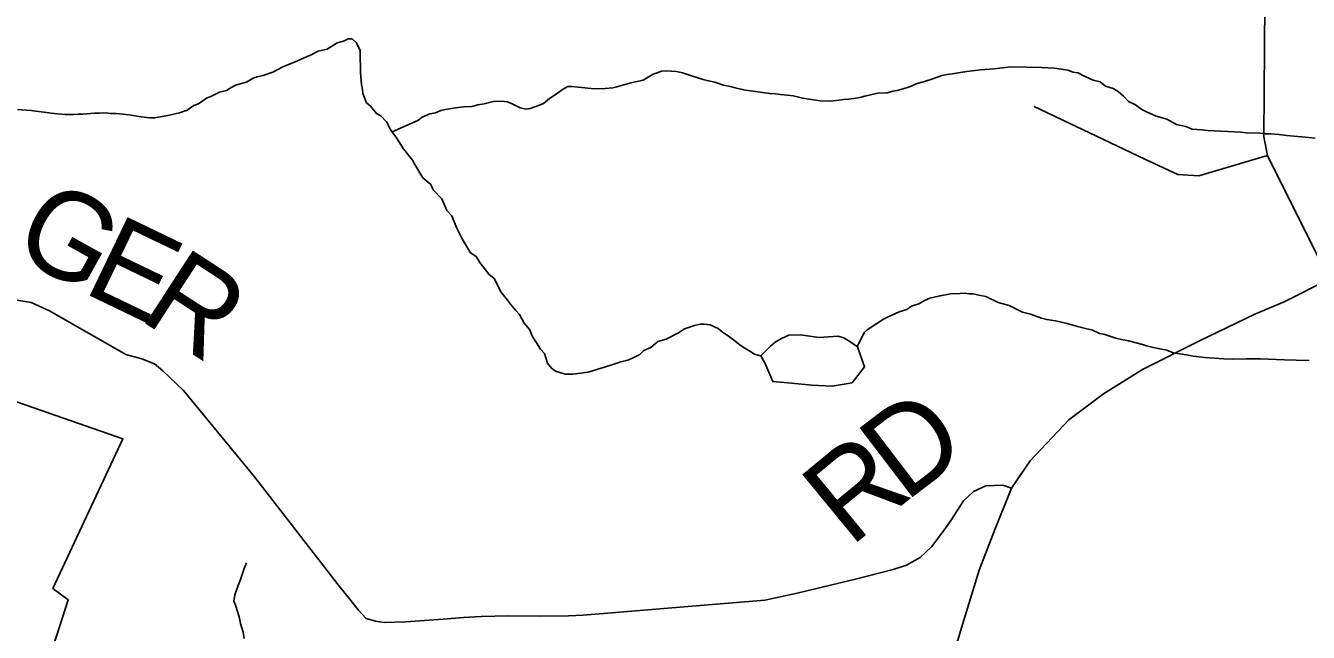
# Model space of a CAD drawing. Extents: x 0 to 34, y 0 to 22.
# Drawn here: x 5.409 to 6.245, y 18.159 to 18.554 of the extents above; entities that cross this region are included whole.
import ezdxf

# ---------------------------------------------------------------- set-up
doc = ezdxf.new("R2010")
doc.units = 0
for name, color, linetype in [('GM_X_Corporation', 7, 'Continuous'), ('GM_X_County_Road', 7, 'Continuous'), ('GM_X_County_Road_Text', 7, 'Continuous'), ('GM_X_Minor_Lake', 7, 'Continuous'), ('GM_X_Minor_River', 7, 'Continuous'), ('GM_X_State_Route', 7, 'Continuous'), ('GM_X_Township_Road', 7, 'Continuous')]:
    doc.layers.add(name, color=color, linetype=linetype)

msp = doc.modelspace()

# ---------------------------------------------------------------- linework, layer by layer
at = {"layer": 'GM_X_Corporation'}
msp.add_lwpolyline([(5.3549, 18.32564), (5.47199, 18.28501), (5.42634, 18.18738), (5.4363, 18.18011), (5.32143, 17.82351)], dxfattribs=at)
at = {"layer": 'GM_X_County_Road'}
for points in [[(5.40285, 18.37527), (5.41202, 18.37394), (5.42418, 18.36853), (5.47376, 18.34003), (5.48429, 18.33709), (5.49254, 18.33384), (5.49773, 18.32953), (5.51151, 18.3165), (5.55767, 18.26031), (5.61323, 18.18866), (5.61971, 18.18073), (5.62535, 18.17342), (5.63061, 18.16777), (5.63663, 18.16609), (5.64229, 18.16519), (5.65629, 18.1658), (5.68067, 18.16749), (5.69403, 18.16847), (5.70553, 18.16913), (5.72358, 18.16956), (5.74326, 18.16929), (5.76254, 18.16962), (5.77202, 18.17013), (5.89051, 18.17992), (5.91147, 18.1843), (5.94961, 18.19356), (5.97403, 18.19975), (5.98282, 18.20255), (5.99167, 18.20764), (5.99906, 18.21465), (6.00639, 18.22433)], [(6.00639, 18.22433), (6.01006, 18.22917), (6.01213, 18.23239), (6.01994, 18.24447), (6.02655, 18.25075), (6.0346, 18.25433), (6.0456, 18.2548), (6.05132, 18.25276)]]:
    msp.add_lwpolyline(points, dxfattribs=at)
at = {"layer": 'GM_X_Minor_Lake'}
for points in [[(5.91362, 18.35281), (5.90601, 18.35256), (5.9014, 18.35036), (5.89711, 18.34796), (5.89416, 18.34536), (5.88788, 18.33913)], [(5.88788, 18.33913), (5.89048, 18.33459), (5.89559, 18.32234), (5.90775, 18.32136), (5.92104, 18.31999), (5.93434, 18.31938), (5.94731, 18.32143), (5.95549, 18.33193), (5.95077, 18.34494), (5.94656, 18.34808), (5.94184, 18.35091), (5.93796, 18.352), (5.92576, 18.35108), (5.91362, 18.35281)]]:
    msp.add_lwpolyline(points, dxfattribs=at)
at = {"layer": 'GM_X_Minor_River'}
for points in [[(5.50887, 18.49741), (5.51384, 18.49923), (5.51808, 18.5022), (5.52113, 18.50328), (5.52652, 18.50699), (5.5292, 18.50809), (5.53495, 18.51103), (5.53953, 18.51209), (5.54299, 18.51431), (5.54606, 18.51578), (5.55255, 18.51757), (5.55678, 18.52015), (5.55945, 18.52087), (5.56327, 18.52194), (5.56977, 18.52411), (5.57629, 18.52742), (5.57935, 18.52889), (5.58433, 18.5307), (5.59161, 18.53399), (5.59429, 18.53509), (5.59927, 18.53766), (5.605, 18.53908), (5.61153, 18.54315), (5.61573, 18.54422), (5.6188, 18.54568), (5.62146, 18.54564), (5.62408, 18.54331), (5.62666, 18.53832), (5.62659, 18.53452), (5.62683, 18.52615), (5.62679, 18.52348), (5.62742, 18.51587), (5.62813, 18.51281), (5.62846, 18.51014), (5.63064, 18.50402), (5.63364, 18.50168), (5.63736, 18.49705), (5.64, 18.49549), (5.64374, 18.49162), (5.64669, 18.48624), (5.65041, 18.48123), (5.65484, 18.47393), (5.6608, 18.46659), (5.66228, 18.46391), (5.66745, 18.45507), (5.6727, 18.45079), (5.67416, 18.44734), (5.67977, 18.44154), (5.68306, 18.43387), (5.68642, 18.43039), (5.68933, 18.42273), (5.69118, 18.41928), (5.69301, 18.41544), (5.69856, 18.40622), (5.70232, 18.40387), (5.70454, 18.40003), (5.71049, 18.39232), (5.71387, 18.38959), (5.71645, 18.38498), (5.71828, 18.38077), (5.72275, 18.37536), (5.72461, 18.37267), (5.72796, 18.36881), (5.73058, 18.3661), (5.73352, 18.36034), (5.73725, 18.35609), (5.7387, 18.35188), (5.74167, 18.34765), (5.74426, 18.34342), (5.74688, 18.34071), (5.74867, 18.33421), (5.75128, 18.33112), (5.75391, 18.32917), (5.76034, 18.32716), (5.76528, 18.32707), (5.77519, 18.32842), (5.78665, 18.33202), (5.79009, 18.3331), (5.79659, 18.33527), (5.80117, 18.33633), (5.80462, 18.33779), (5.80884, 18.34), (5.81154, 18.34261), (5.81614, 18.34443), (5.82077, 18.34854), (5.82611, 18.34996), (5.83416, 18.354), (5.83801, 18.3566), (5.84451, 18.35877), (5.84833, 18.35984), (5.85099, 18.35979), (5.85478, 18.35935), (5.86007, 18.35697), (5.86269, 18.35464), (5.86682, 18.35191), (5.87095, 18.34879), (5.87433, 18.34607), (5.87734, 18.34412), (5.88073, 18.34216), (5.88373, 18.3402), (5.88676, 18.33939)], [(5.64747, 18.48518), (5.66428, 18.4924), (5.66698, 18.49463), (5.67196, 18.49683), (5.67577, 18.49752), (5.67922, 18.49898), (5.68227, 18.49969), (5.68875, 18.50071), (5.69408, 18.50138), (5.69941, 18.50167), (5.70323, 18.50274), (5.70742, 18.50343), (5.71353, 18.50484), (5.71886, 18.50513), (5.72265, 18.50468), (5.72529, 18.5035), (5.73095, 18.50073), (5.73474, 18.49991), (5.73741, 18.50024), (5.74352, 18.50241), (5.7462, 18.50351), (5.75006, 18.50686), (5.75506, 18.5102), (5.75853, 18.5128), (5.76198, 18.51464), (5.76464, 18.51459), (5.76881, 18.51414), (5.77944, 18.51319), (5.78629, 18.51345), (5.79124, 18.51375), (5.79391, 18.51446), (5.80308, 18.51696), (5.81109, 18.51872), (5.81762, 18.52279), (5.8203, 18.5235), (5.82298, 18.5246), (5.8264, 18.52492), (5.83286, 18.52442), (5.83665, 18.5236), (5.84005, 18.5224), (5.84269, 18.52159), (5.85026, 18.51917), (5.85366, 18.51835), (5.85783, 18.51752), (5.8635, 18.51552), (5.86805, 18.51468), (5.87108, 18.51386), (5.87487, 18.51303), (5.87789, 18.51222), (5.88434, 18.51135), (5.89041, 18.51048), (5.89382, 18.51004), (5.89724, 18.50998), (5.90066, 18.50954), (5.90521, 18.50908), (5.90901, 18.50863), (5.91241, 18.50781), (5.91506, 18.507), (5.92075, 18.50614), (5.92644, 18.50528), (5.93328, 18.50516), (5.93861, 18.50583), (5.94166, 18.50615), (5.94509, 18.50647), (5.94813, 18.5068), (5.95233, 18.50749), (5.95653, 18.50855), (5.96416, 18.51032), (5.97025, 18.5106), (5.97407, 18.51167), (5.97673, 18.512), (5.98055, 18.51308), (5.98476, 18.51453), (5.98974, 18.51672), (5.99394, 18.51779), (6.00005, 18.51958), (6.00579, 18.52176), (6.00923, 18.52246), (6.01418, 18.52314), (6.01799, 18.52383), (6.02219, 18.52452), (6.03095, 18.5255), (6.0397, 18.52611), (6.05113, 18.52743), (6.07089, 18.52708), (6.07925, 18.52656), (6.08797, 18.52526), (6.09137, 18.52406), (6.09479, 18.52362), (6.09742, 18.52205), (6.10459, 18.51888), (6.10913, 18.51766), (6.11251, 18.51494), (6.11742, 18.51333), (6.12081, 18.51137), (6.12418, 18.50827), (6.12755, 18.50479), (6.13207, 18.50281), (6.1362, 18.49969), (6.13922, 18.49812), (6.14563, 18.49534)], [(5.40322, 18.49965), (5.40891, 18.49917), (5.41233, 18.49911), (5.41499, 18.49869), (5.42068, 18.49783), (5.42523, 18.49736), (5.42941, 18.49691), (5.43434, 18.49644), (5.43966, 18.49635), (5.44271, 18.49668), (5.44575, 18.49662), (5.45336, 18.49725), (5.4564, 18.4972), (5.46059, 18.4975), (5.46362, 18.49707), (5.46742, 18.497), (5.47198, 18.49654), (5.47615, 18.49609), (5.48108, 18.49524), (5.48374, 18.49481), (5.48943, 18.49433), (5.49285, 18.49427), (5.49629, 18.49497), (5.50238, 18.49601), (5.50887, 18.49741)], [(6.14563, 18.49534), (6.15244, 18.49332), (6.15885, 18.48979), (6.16491, 18.48854), (6.16906, 18.48694), (6.17514, 18.48645), (6.17893, 18.48601), (6.18767, 18.48547), (6.19223, 18.48539), (6.20058, 18.48487), (6.20438, 18.48442), (6.2135, 18.48426), (6.21653, 18.48382), (6.22033, 18.48376), (6.22565, 18.48328), (6.23058, 18.48282), (6.24045, 18.48188), (6.24918, 18.48097)], [(5.95072, 18.34497), (5.95518, 18.35433), (5.95718, 18.35598), (5.96353, 18.3601), (5.96776, 18.36307), (5.97083, 18.36453), (5.97811, 18.36783), (5.98307, 18.36926), (5.98615, 18.37149), (5.99074, 18.37293), (5.99458, 18.37515), (5.99802, 18.37661), (6.00375, 18.37803), (6.01137, 18.37941), (6.01784, 18.37968), (6.02089, 18.38001), (6.02354, 18.37958), (6.0262, 18.37953), (6.02999, 18.37871), (6.03454, 18.37786), (6.04246, 18.37392), (6.04965, 18.3719), (6.05832, 18.36756), (6.06362, 18.36632), (6.0708, 18.36354), (6.0742, 18.36271), (6.07989, 18.36185), (6.08747, 18.3602), (6.09428, 18.35818), (6.09768, 18.35736), (6.10412, 18.35572), (6.10865, 18.35374), (6.11206, 18.35292), (6.11924, 18.35051), (6.12303, 18.34968), (6.12757, 18.34884), (6.1325, 18.34761), (6.13666, 18.3464), (6.1393, 18.34559), (6.14271, 18.34477), (6.14688, 18.34394), (6.15256, 18.3427), (6.15672, 18.3411), (6.16544, 18.33981), (6.16961, 18.33898), (6.1772, 18.33808), (6.18327, 18.33759), (6.18973, 18.3371), (6.19505, 18.33701), (6.20455, 18.33722), (6.21368, 18.33706), (6.22925, 18.33641), (6.23685, 18.33627), (6.24522, 18.33612)], [(5.88676, 18.33939), (5.88788, 18.33913)], [(5.551, 18.15475), (5.5503, 18.15894), (5.5485, 18.16468), (5.54781, 18.16888), (5.54528, 18.17653), (5.54418, 18.17921), (5.54501, 18.18338), (5.54702, 18.18943), (5.5486, 18.1932), (5.551, 18.20039), (5.55259, 18.20416)]]:
    msp.add_lwpolyline(points, dxfattribs=at)
at = {"layer": 'GM_X_State_Route'}
for points in [[(6.22994, 18.37483), (6.25836, 18.38904)], [(5.99764, 18.09513), (6.00093, 18.1035), (6.01091, 18.13568), (6.02012, 18.16674), (6.03019, 18.19927), (6.04054, 18.22638), (6.05132, 18.25276), (6.06351, 18.27063), (6.08855, 18.29736), (6.11114, 18.3143), (6.13656, 18.33012), (6.17383, 18.34894), (6.20979, 18.36626), (6.22899, 18.37436), (6.22994, 18.37483)]]:
    msp.add_lwpolyline(points, dxfattribs=at)
at = {"layer": 'GM_X_Township_Road'}
for points in [[(6.25836, 18.38904), (6.21807, 18.46961), (6.21585, 18.48193), (6.21649, 18.5693), (6.21627, 18.61541), (6.21188, 18.62209)], [(6.06596, 18.50162), (6.13825, 18.46736), (6.15971, 18.45719), (6.17327, 18.45644), (6.21807, 18.46961)]]:
    msp.add_lwpolyline(points, dxfattribs=at)

# ---------------------------------------------------------------- texts
at = {"layer": 'GM_X_County_Road_Text'}
for s, rotation, p in [('G', 330.97264, (5.3978, 18.40693)), ('E', 334.2762, (5.4447, 18.38102)), ('R', 326.98219, (5.48132, 18.36351)), ('D', 37.32671, (5.98172, 18.24316)), ('R', 39.43577, (5.94611, 18.21386))]:
    msp.add_text(s, height=0.05682, rotation=rotation, dxfattribs=at).set_placement(p)

doc.saveas('drawing.dxf')
